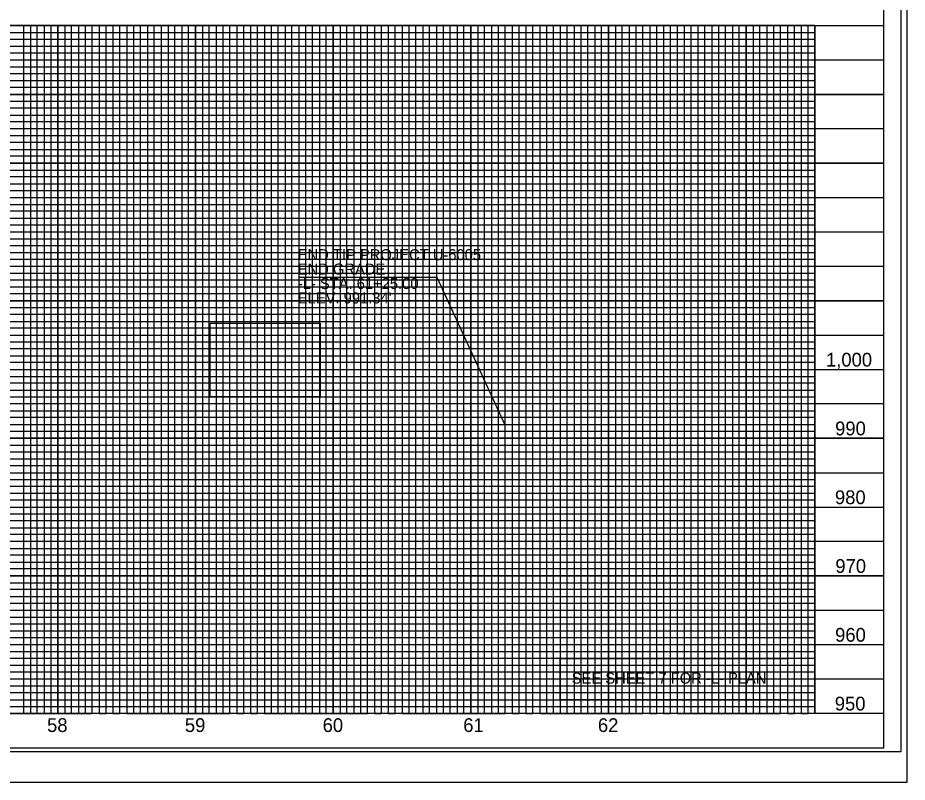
# Model space of a CAD drawing. Extents: x 1626113 to 1628102, y 900759 to 901859.
# Drawn here: x 1627151 to 1627797, y 900759 to 901315 of the extents above; entities that cross this region are included whole.
import ezdxf

# ---------------------------------------------------------------- set-up
doc = ezdxf.new("R2010")
doc.units = 0
for name, color, linetype in [('Default', 7, 'Continuous'), ('Prop DSN Text', 7, 'Continuous'), ('Prop PHM Black Shape', 7, 'Continuous'), ('Prop Plan Preparation Cover Label', 7, 'Continuous'), ('Prop VPI Label', 7, 'Continuous'), ('Scratch_Level_2', 7, 'Continuous'), ('Sheet Cutting Line CELL', 7, 'Continuous'), ('Sheet DOT Grid CELL', 7, 'Continuous'), ('Sheet Layout Profile Border Port 2', 7, 'Continuous'), ('Sheet Plot Border Inside CELL', 7, 'Continuous'), ('Sheet Plot Border Outside CELL', 7, 'Continuous'), ('Sheet Profile CELL', 7, 'Continuous'), ('Sheet Profile Grid Major CELL', 7, 'Continuous'), ('Sheet Profile Grid Middle CELL', 7, 'Continuous')]:
    doc.layers.add(name, color=color, linetype=linetype)

msp = doc.modelspace()

# ---------------------------------------------------------------- linework, layer by layer
at = {"layer": 'Prop DSN Text'}
msp.add_lwpolyline([(1627544.95, 900849.2), (1627709.95, 900849.2), (1627709.95, 900819.2), (1627544.95, 900819.2)], close=True, dxfattribs=at)
at = {"layer": 'Prop PHM Black Shape'}
for points in [[(1627290.68, 901092.78), (1627370.6, 901092.78), (1627370.6, 901039.24), (1627290.68, 901039.24)], [(1627544.95, 900849.2), (1627709.95, 900849.2), (1627709.95, 900819.2), (1627544.95, 900819.2)]]:
    msp.add_lwpolyline(points, close=True, dxfattribs=at)
at = {"layer": 'Prop Plan Preparation Cover Label'}
for p, q in [((1626329.95, 901304.2), (1627729.95, 901304.2)), ((1627729.95, 901299.2), (1626329.95, 901299.2)), ((1626329.95, 901294.2), (1627729.95, 901294.2)), ((1627729.95, 901289.2), (1626329.95, 901289.2)), ((1626329.95, 901279.2), (1627729.95, 901279.2)), ((1627729.95, 901274.2), (1626329.95, 901274.2)), ((1626329.95, 901269.2), (1627729.95, 901269.2)), ((1627729.95, 901264.2), (1626329.95, 901264.2)), ((1626329.95, 901254.2), (1627729.95, 901254.2)), ((1627729.95, 901249.2), (1626329.95, 901249.2)), ((1626329.95, 901244.2), (1627729.95, 901244.2)), ((1627729.95, 901239.2), (1626329.95, 901239.2)), ((1626329.95, 901229.2), (1627729.95, 901229.2)), ((1627729.95, 901224.2), (1626329.95, 901224.2)), ((1626329.95, 901219.2), (1627729.95, 901219.2)), ((1627729.95, 901214.2), (1626329.95, 901214.2)), ((1626329.95, 901204.2), (1627729.95, 901204.2)), ((1627729.95, 901199.2), (1626329.95, 901199.2)), ((1626329.95, 901194.2), (1627729.95, 901194.2)), ((1627729.95, 901189.2), (1626329.95, 901189.2)), ((1626329.95, 901179.2), (1627729.95, 901179.2)), ((1627729.95, 901174.2), (1626329.95, 901174.2)), ((1626329.95, 901169.2), (1627729.95, 901169.2)), ((1627729.95, 901164.2), (1626329.95, 901164.2)), ((1626329.95, 901154.2), (1627729.95, 901154.2)), ((1627729.95, 901149.2), (1626329.95, 901149.2)), ((1626329.95, 901144.2), (1627729.95, 901144.2)), ((1627729.95, 901139.2), (1626329.95, 901139.2)), ((1626329.95, 901129.2), (1627729.95, 901129.2)), ((1627729.95, 901124.2), (1626329.95, 901124.2)), ((1626329.95, 901119.2), (1627729.95, 901119.2)), ((1627729.95, 901114.2), (1626329.95, 901114.35)), ((1626329.95, 901104.2), (1627729.95, 901104.2)), ((1627729.95, 901099.2), (1626329.95, 901099.2)), ((1626329.95, 901094.2), (1627729.95, 901094.2)), ((1627729.95, 901089.2), (1626329.95, 901089.2)), ((1626329.95, 901079.2), (1627729.95, 901079.2)), ((1627729.95, 901074.2), (1626329.95, 901074.2)), ((1626329.95, 901069.2), (1627729.95, 901069.2)), ((1627729.95, 901064.2), (1626329.95, 901064.2)), ((1626329.95, 901054.2), (1627729.95, 901054.2)), ((1627729.95, 901049.2), (1626329.95, 901049.2)), ((1626329.95, 901044.2), (1627729.95, 901044.2)), ((1627729.95, 901039.2), (1626329.95, 901039.2)), ((1626329.95, 901029.2), (1627729.95, 901029.2)), ((1627729.95, 901024.2), (1626329.95, 901024.2)), ((1626329.95, 901019.2), (1627729.95, 901019.2)), ((1627729.95, 901014.2), (1626329.95, 901014.2)), ((1626329.95, 901004.2), (1627729.95, 901004.2)), ((1627729.95, 900999.2), (1626329.95, 900999.2)), ((1626329.95, 900994.2), (1627729.95, 900994.2)), ((1627729.95, 900989.2), (1626329.95, 900989.2)), ((1626329.95, 900979.2), (1627729.95, 900979.2)), ((1627729.95, 900974.2), (1626329.95, 900974.2)), ((1626329.95, 900969.2), (1627729.95, 900969.2)), ((1627729.95, 900964.2), (1626329.95, 900964.2)), ((1626329.95, 900954.2), (1627729.95, 900954.2)), ((1627729.95, 900949.2), (1626329.95, 900949.2)), ((1626329.95, 900944.2), (1627729.95, 900944.2)), ((1627729.95, 900939.2), (1626329.95, 900939.2)), ((1626329.95, 900929.2), (1627729.95, 900929.2)), ((1627729.95, 900924.2), (1626329.95, 900924.2)), ((1626329.95, 900919.2), (1627729.95, 900919.2)), ((1627729.95, 900914.2), (1626329.95, 900914.2)), ((1626329.95, 900904.2), (1627729.95, 900904.2)), ((1627729.95, 900899.2), (1626329.95, 900899.2)), ((1626329.95, 900894.2), (1627729.95, 900894.2)), ((1627729.95, 900889.2), (1626329.95, 900889.2)), ((1626329.95, 900879.2), (1627729.95, 900879.2)), ((1627729.95, 900874.2), (1626329.95, 900874.2)), ((1626329.95, 900869.2), (1627729.95, 900869.2)), ((1627729.95, 900864.2), (1626329.95, 900864.2)), ((1626329.95, 900854.2), (1627729.95, 900854.2)), ((1627729.95, 900849.2), (1626329.95, 900849.2)), ((1626329.95, 900844.2), (1627729.95, 900844.2)), ((1627729.95, 900839.2), (1626329.95, 900839.2)), ((1626329.95, 900829.2), (1627729.95, 900829.2)), ((1627729.95, 900824.2), (1626329.95, 900824.2)), ((1626329.95, 900819.2), (1627729.95, 900819.2)), ((1626329.95, 900814.2), (1627729.95, 900814.2)), ((1627729.95, 900814.2), (1627729.95, 900814.2))]:
    msp.add_line(p, q, dxfattribs=at)
for points in [[(1627149.95, 901309.2), (1627159.95, 901309.2), (1627159.95, 900809.2), (1627164.95, 900809.2)], [(1627164.95, 900809.2), (1627164.95, 901309.2), (1627169.95, 901309.2), (1627169.95, 900809.2), (1627174.95, 900809.2), (1627174.95, 901309.2), (1627184.95, 901309.2), (1627184.95, 900809.2), (1627189.95, 900809.2), (1627189.95, 901309.2), (1627194.95, 901309.2), (1627194.95, 900809.2), (1627199.95, 900809.2), (1627199.95, 901309.2), (1627209.95, 901309.2), (1627209.95, 900809.2), (1627214.95, 900809.2), (1627214.95, 901309.2), (1627219.95, 901309.2), (1627219.95, 900809.2), (1627224.95, 900809.2), (1627224.95, 901309.2), (1627234.95, 901309.2), (1627234.95, 900809.2), (1627239.95, 900809.2), (1627239.95, 901309.2), (1627244.95, 901309.2), (1627244.95, 900809.2), (1627249.95, 900809.2), (1627249.95, 901309.2), (1627259.95, 901309.2), (1627259.95, 900809.2), (1627264.95, 900809.2), (1627264.95, 901309.2), (1627269.95, 901309.2), (1627269.95, 900809.2), (1627274.95, 900809.2), (1627274.95, 901309.2), (1627284.95, 901309.2), (1627284.95, 900809.2), (1627289.95, 900809.2), (1627289.95, 901309.2), (1627294.95, 901309.2), (1627294.95, 900809.2), (1627299.95, 900809.2), (1627299.95, 901309.2), (1627309.95, 901309.2), (1627309.95, 900809.2), (1627314.95, 900809.2), (1627314.95, 901309.2), (1627319.95, 901309.2), (1627319.95, 900809.2), (1627324.95, 900809.2), (1627324.95, 901309.2), (1627334.95, 901309.2), (1627334.95, 900809.2), (1627339.95, 900809.2), (1627339.95, 901309.2), (1627344.95, 901309.2), (1627344.95, 900809.2), (1627349.95, 900809.2), (1627349.95, 901309.2), (1627359.95, 901309.2), (1627359.95, 900809.2), (1627364.95, 900809.2), (1627364.95, 901309.2), (1627369.95, 901309.2), (1627369.95, 900809.2), (1627374.95, 900809.2), (1627374.95, 901309.2), (1627384.95, 901309.2), (1627384.95, 900809.2), (1627389.95, 900809.2), (1627389.95, 901309.2), (1627394.95, 901309.2), (1627394.95, 900809.2), (1627399.95, 900809.2), (1627399.95, 901309.2), (1627409.95, 901309.2), (1627409.95, 900809.2), (1627414.95, 900809.2), (1627414.95, 901309.2), (1627419.95, 901309.2), (1627419.95, 900809.2), (1627424.95, 900809.2), (1627424.95, 901309.2), (1627434.95, 901309.2), (1627434.95, 900809.2), (1627439.95, 900809.2), (1627439.95, 901309.2), (1627444.95, 901309.2), (1627444.95, 900809.2), (1627449.95, 900809.2), (1627449.95, 901309.2), (1627459.95, 901309.2), (1627459.95, 900809.2), (1627464.95, 900809.2), (1627464.95, 901309.2), (1627469.95, 901309.2), (1627469.95, 900809.2)], [(1627469.95, 900809.2), (1627474.95, 900809.2), (1627474.95, 901309.2), (1627484.95, 901309.2), (1627484.95, 900809.2), (1627489.95, 900809.2), (1627489.95, 901309.2), (1627494.95, 901309.2), (1627494.95, 900809.2), (1627499.95, 900809.2), (1627499.95, 901309.2), (1627509.95, 901309.2), (1627509.95, 900809.2), (1627514.95, 900809.2), (1627514.95, 901309.2), (1627519.95, 901309.2), (1627519.95, 900809.2), (1627524.95, 900809.2), (1627524.95, 901309.2), (1627534.95, 901309.2), (1627534.95, 900809.2), (1627539.95, 900809.2), (1627539.95, 901309.2), (1627544.95, 901309.2), (1627544.95, 900809.2), (1627549.95, 900809.2), (1627549.95, 901309.2), (1627559.95, 901309.2), (1627559.95, 900809.2), (1627564.95, 900809.2), (1627564.95, 901309.2), (1627569.95, 901309.2), (1627569.95, 900809.2), (1627574.95, 900809.2), (1627574.95, 901309.2), (1627584.95, 901309.2), (1627584.95, 900809.2), (1627589.95, 900809.2), (1627589.95, 901309.2), (1627594.95, 901309.2), (1627594.95, 900809.2), (1627599.95, 900809.2), (1627599.95, 901309.2), (1627609.95, 901309.2), (1627609.95, 900809.2), (1627614.95, 900809.2), (1627614.95, 901309.2), (1627619.95, 901309.2), (1627619.95, 900809.2), (1627624.95, 900809.2), (1627624.95, 901309.2), (1627634.95, 901309.2), (1627634.95, 900809.2), (1627639.95, 900809.2), (1627639.95, 901309.2), (1627644.95, 901309.2), (1627644.95, 900809.2), (1627649.95, 900809.2), (1627649.95, 901309.2), (1627659.95, 901309.2), (1627659.95, 900809.2), (1627664.95, 900809.2), (1627664.95, 901309.2), (1627669.95, 901309.2), (1627669.95, 900809.2), (1627674.95, 900809.2), (1627674.95, 901309.2), (1627684.95, 901309.2), (1627684.95, 900809.2), (1627689.95, 900809.2), (1627689.95, 901309.2), (1627694.95, 901309.2), (1627694.95, 900809.2), (1627699.95, 900809.2), (1627699.95, 901309.2), (1627709.95, 901309.2), (1627709.95, 900809.2), (1627714.95, 900809.2), (1627714.95, 901309.2), (1627719.95, 901309.2), (1627719.95, 900809.2), (1627724.95, 900809.2), (1627724.95, 901309.2), (1627729.95, 901309.2)]]:
    msp.add_lwpolyline(points, dxfattribs=at)
at = {"layer": 'Prop VPI Label'}
msp.add_lwpolyline([(1627504.95, 901018.63), (1627455.51, 901126.04), (1627355.51, 901126.04)], dxfattribs=at)
at = {"layer": 'Scratch_Level_2'}
msp.add_lwpolyline([(1626379.95, 900809.45), (1627729.95, 900809.45), (1627729.95, 901309.2), (1626379.95, 901309.2)], close=True, dxfattribs=at)
at = {"layer": 'Sheet Cutting Line CELL'}
msp.add_line((1626112.95, 900759.2), (1627796.95, 900759.2), dxfattribs=at)
at = {"layer": 'Sheet DOT Grid CELL'}
for p, q in [((1626279.95, 901309.2), (1627779.83, 901309.2)), ((1627179.95, 901309.2), (1627179.95, 900809.2)), ((1627229.95, 901309.2), (1627229.95, 900809.2)), ((1627279.95, 901309.2), (1627279.95, 900809.2)), ((1627329.95, 901309.2), (1627329.95, 900809.2)), ((1627379.95, 901309.2), (1627379.95, 900809.2)), ((1627429.95, 901309.2), (1627429.95, 900809.2)), ((1627479.95, 901309.2), (1627479.95, 900809.2)), ((1627529.95, 901309.2), (1627529.95, 900809.2)), ((1627579.95, 901309.2), (1627579.95, 900809.2)), ((1627629.95, 901309.2), (1627629.95, 900809.2)), ((1627679.95, 901309.2), (1627679.95, 900809.2)), ((1627729.95, 901309.2), (1627729.95, 900809.2)), ((1626279.95, 901259.2), (1627779.83, 901259.2)), ((1626279.95, 901209.2), (1627779.83, 901209.2)), ((1626279.95, 901159.2), (1627779.83, 901159.2)), ((1626279.95, 901109.2), (1627779.83, 901109.2)), ((1626279.95, 901059.2), (1627779.83, 901059.2)), ((1626279.95, 901009.2), (1627779.83, 901009.2)), ((1626279.95, 900959.2), (1627779.83, 900959.2)), ((1626279.95, 900909.2), (1627779.83, 900909.2)), ((1626279.95, 900859.2), (1627779.83, 900859.2))]:
    msp.add_line(p, q, dxfattribs=at)
at = {"layer": 'Sheet Layout Profile Border Port 2'}
msp.add_lwpolyline([(1626329.95, 901309.2), (1627729.95, 901309.2), (1627729.95, 900809.2), (1626329.95, 900809.2)], close=True, dxfattribs=at)
at = {"layer": 'Sheet Plot Border Inside CELL'}
msp.add_lwpolyline([(1626125.95, 900781.65), (1627792.45, 900781.65), (1627792.45, 901836.75), (1626125.95, 901836.75)], close=True, dxfattribs=at)
at = {"layer": 'Sheet Plot Border Outside CELL'}
msp.add_lwpolyline([(1626112.95, 900759.2), (1627796.95, 900759.2), (1627796.95, 901859.2), (1626112.95, 901859.2)], close=True, dxfattribs=at)
at = {"layer": 'Sheet Profile CELL'}
for p, q in [((1626279.95, 901309.2), (1627779.95, 901309.2)), ((1627779.95, 900809.2), (1626279.95, 900809.2)), ((1626279.95, 900784.2), (1627779.95, 900784.2))]:
    msp.add_line(p, q, dxfattribs=at)
msp.add_lwpolyline([(1627779.95, 901834.2), (1626279.95, 901834.2), (1626279.95, 900784.2), (1627779.95, 900784.2)], close=True, dxfattribs=at)
at = {"layer": 'Sheet Profile Grid Major CELL'}
for p, q in [((1627179.95, 901309.2), (1627229.95, 901309.2)), ((1627279.95, 901309.2), (1627329.95, 901309.2)), ((1627379.95, 901309.2), (1627429.95, 901309.2)), ((1627479.95, 901309.2), (1627529.95, 901309.2)), ((1627579.95, 901309.2), (1627629.95, 901309.2)), ((1627679.95, 901309.2), (1627729.95, 901309.2)), ((1627679.95, 900809.2), (1627679.95, 900809.2))]:
    msp.add_line(p, q, dxfattribs=at)
for points in [[(1627129.95, 900809.2), (1627179.95, 900809.2), (1627179.95, 901309.2), (1627229.95, 901309.2), (1627229.95, 900809.2), (1627279.95, 900809.2), (1627279.95, 901309.2), (1627329.95, 901309.2), (1627329.95, 900809.2), (1627379.95, 900809.2), (1627379.95, 901309.2), (1627429.95, 901309.2), (1627429.95, 900809.2), (1627479.95, 900809.2), (1627479.95, 901309.2), (1627529.95, 901309.2), (1627529.95, 900809.2), (1627579.95, 900809.2), (1627579.95, 901309.2), (1627629.95, 901309.2), (1627629.95, 900809.2), (1627679.95, 900809.2), (1627679.95, 900809.2), (1627679.95, 901309.2), (1627729.95, 901309.2), (1627729.95, 900809.2)], [(1627779.95, 901259.2), (1626279.95, 901259.2)], [(1627779.95, 901209.2), (1626279.95, 901209.2), (1626279.95, 901159.2), (1627779.95, 901159.2)], [(1627779.95, 901109.2), (1626279.95, 901109.2), (1626279.95, 901059.2), (1627779.95, 901059.2)], [(1627779.95, 901009.2), (1626279.95, 901009.2), (1626279.95, 900959.2), (1627779.95, 900959.2)], [(1627779.95, 900909.2), (1626279.95, 900909.2), (1626279.95, 900909.2), (1626279.95, 900859.2), (1627779.95, 900859.2)], [(1627779.95, 900809.2), (1626279.95, 900809.2)]]:
    msp.add_lwpolyline(points, dxfattribs=at)
at = {"layer": 'Sheet Profile Grid Middle CELL'}
for points in [[(1627104.95, 901309.2), (1627154.95, 901309.2), (1627154.95, 900809.2), (1627204.95, 900809.2), (1627204.95, 901309.2), (1627254.95, 901309.2), (1627254.95, 900809.2), (1627304.95, 900809.2), (1627304.95, 901309.2), (1627354.95, 901309.2), (1627354.95, 900809.2), (1627404.95, 900809.2), (1627404.95, 901309.2), (1627454.95, 901309.2), (1627454.95, 900809.2), (1627504.95, 900809.2), (1627504.95, 901309.2), (1627554.95, 901309.2), (1627554.95, 900809.2), (1627604.95, 900809.2), (1627604.95, 901309.2), (1627654.95, 901309.2), (1627654.95, 900809.2), (1627704.95, 900809.2), (1627704.95, 901309.2)], [(1626279.95, 901284.2), (1627779.95, 901284.2)], [(1627779.95, 901234.2), (1626279.95, 901234.2), (1626279.95, 901184.2), (1627779.95, 901184.2)], [(1627779.95, 901134.2), (1626279.95, 901134.2), (1626279.95, 901084.2), (1627779.95, 901084.2)], [(1627779.95, 901034.2), (1626279.95, 901034.2), (1626279.95, 900984.2), (1627779.95, 900984.2)], [(1627779.95, 900934.2), (1626279.95, 900934.2), (1626279.95, 900884.2), (1627779.95, 900884.2)], [(1627779.95, 900834.2), (1626279.95, 900834.2)]]:
    msp.add_lwpolyline(points, dxfattribs=at)

# ---------------------------------------------------------------- texts
at = {"layer": 'Default'}
for s, p in [('1,000', (1627737.96, 901061.34)), ('990', (1627744.56, 901011.34)), ('980', (1627744.45, 900961.34)), ('970', (1627744.73, 900911.34)), ('960', (1627744.56, 900861.34)), ('950', (1627744.34, 900811.34)), ('58', (1627172.09, 900795.7)), ('59', (1627272.2, 900795.7)), ('60', (1627372.28, 900795.7)), ('61', (1627474.42, 900795.7)), ('62', (1627572.25, 900795.7))]:
    msp.add_text(s, height=10, dxfattribs=at).set_placement(p)
at = {"layer": 'Prop DSN Text'}
msp.add_text('SEE SHEET 7 FOR -L- PLAN', height=8, dxfattribs=at).set_placement((1627553.22, 900830.9))
at = {"layer": 'Prop VPI Label'}
for s, p in [('END TIP PROJECT U-6005', (1627354.23, 901138.69)), ('END GRADE', (1627354.23, 901128.2)), ('-L- STA. 61+25.00', (1627354.23, 901117.71)), ("ELEV. 991.34'", (1627354.23, 901107.22))]:
    msp.add_text(s, height=8, dxfattribs=at).set_placement(p)

doc.saveas('drawing.dxf')
